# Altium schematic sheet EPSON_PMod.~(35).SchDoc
size A4
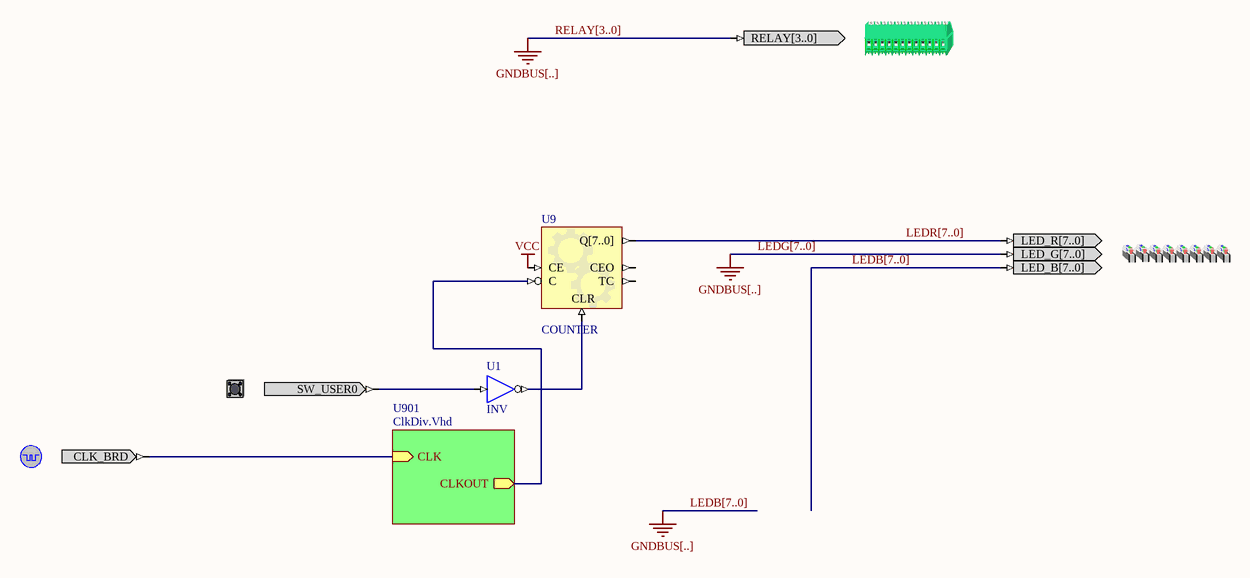
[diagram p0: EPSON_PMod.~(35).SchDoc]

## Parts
(Parts that share a designator on the sheet are numbered #1, #2 ... from top to bottom, then left to right.)
?#1  RELAYCNTR  (value not drawn)
?#2  LEDS_RGB  (value not drawn)
?#3  USER_BUTTON0  (value not drawn)
?#4  CLOCK_BOARD  (value not drawn)
U1  INV
U9  COUNTER

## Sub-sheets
U901 = ClkDiv.Vhd: CLK (in), CLKOUT (out)

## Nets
VCC: U9.CE
Net?#3_SW_USER0: ?#3.SW_USER0 U1.I
Net?#4_CLK_BRD: ?#4.CLK_BRD ; sheet U901/CLK
NetU1_O: U1.O U9.CLR
NetU9_C: U9.C ; sheet U901/CLKOUT

Not connected (* = marked no-connect by the designer): ?#1 RELAY[3..0]; ?#2 LED_B[7..0] LED_G[7..0] LED_R[7..0]; U9 CEO Q[7..0] TC

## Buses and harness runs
bus LEDB[7..0]
bus LEDG[7..0]
bus LEDR[7..0]
bus RELAY[3..0]

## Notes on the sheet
- Labels drawn without touching a wire or pin: GNDBUS[..]

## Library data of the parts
?#1 = RELAYCNTR: RELAY; PortComponent: True
?#2 = LEDS_RGB: LEDS RGB; PortComponent: True
?#3 = USER_BUTTON0: Generic User Button; PortComponent: True
?#4 = CLOCK_BOARD: Global System Clock Supply; PortComponent: True
U1 = INV: Inverter; FunctionalClass: Logic Primitive; ArchiveName: GENERIC; VHDLIB_SIM: GENERIC_LIB
U9 = COUNTER: Configurable Counter; ConfiguratorName: GENERIC_COUNTER; ConfigurationParameters: {}Version[1.0]{}Type[Binary]{}SyncReset[False]{}NegativeClockEdge[True]{}FixedDirection[True]{}IsIncrement[True]{}SignalWidth[8]{}MaxValue[255]{}BusOutput[True]{}Loadable[False]{}BusInput[False]{}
